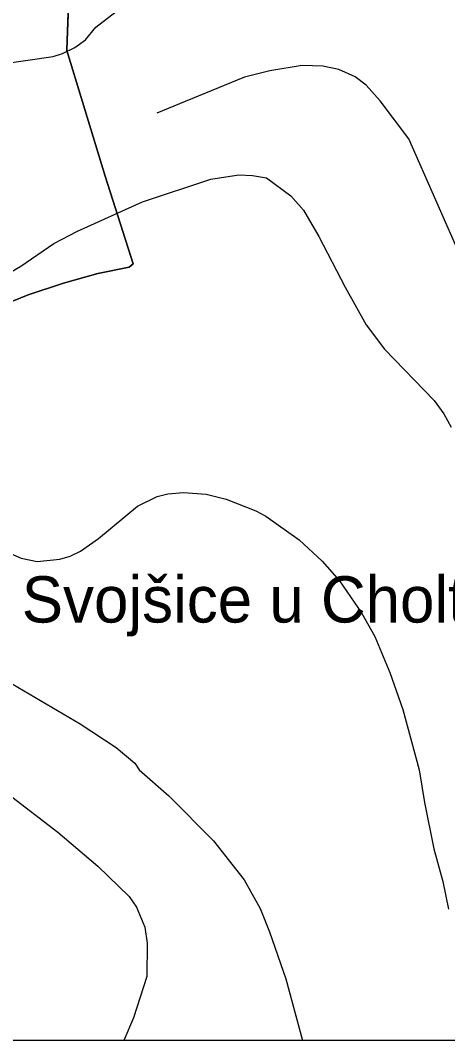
# Model space of a CAD drawing. Extents: x -662620 to -656370, y -1067090 to -1062990.
# Drawn here: x -660856.6 to -660671.9, y -1067089.7 to -1066648.8 of the extents above; entities that cross this region are included whole.
import ezdxf

# ---------------------------------------------------------------- set-up
doc = ezdxf.new("R2010")
doc.units = 0
for name, color, linetype in [('HRANICE_KATASTRÁLNÍHO_ÚZEMÍ', 7, 'Continuous'), ('NÁZEV_K__Ú_', 7, 'Continuous'), ('OBVOD_PÚ', 7, 'Continuous'), ('ORNÁ_PŮDA_-_STÁVAJÍCÍ', 7, 'Continuous'), ('ram', 7, 'Continuous'), ('VRSTEVNICE_ZDŮRAZNĚNÁ', 7, 'Continuous'), ('VRSTEVNICE_ZÁKLADNÍ', 7, 'Continuous')]:
    doc.layers.add(name, color=color, linetype=linetype)

msp = doc.modelspace()

# ---------------------------------------------------------------- linework, layer by layer
at = {"layer": 'HRANICE_KATASTRÁLNÍHO_ÚZEMÍ'}
msp.add_lwpolyline([(-660835.26, -1066626.26), (-660836.34, -1066657.33), (-660836.48, -1066661.71), (-660819.92, -1066716.09), (-660807.8, -1066754), (-660809.6, -1066755.35), (-660823.13, -1066758.13), (-660837.99, -1066762.32), (-660853.18, -1066767.38), (-660870, -1066774.16), (-660885.13, -1066781.19), (-660896.33, -1066786.99), (-660960.7, -1066828.87), (-661014.75, -1066874.85), (-661055.88, -1066910.9), (-661072.7, -1066925.54), (-661106, -1066954.65), (-661122.94, -1066935.93), (-661158.28, -1066916.17), (-661181.17, -1066907.25)], dxfattribs=at)
at = {"layer": 'OBVOD_PÚ'}
for points in [[(-660836.34, -1066657.33), (-660835.26, -1066626.26)], [(-660836.48, -1066661.71), (-660836.34, -1066657.33)], [(-660819.92, -1066716.09), (-660836.48, -1066661.71)], [(-660807.8, -1066754), (-660819.92, -1066716.09)], [(-660823.13, -1066758.13), (-660809.6, -1066755.35)], [(-660809.6, -1066755.35), (-660807.8, -1066754)], [(-660837.99, -1066762.32), (-660823.13, -1066758.13)], [(-660853.18, -1066767.38), (-660837.99, -1066762.32)], [(-660870, -1066774.16), (-660853.18, -1066767.38)]]:
    msp.add_lwpolyline(points, dxfattribs=at)
at = {"layer": 'ORNÁ_PŮDA_-_STÁVAJÍCÍ'}
for p, q in [((-660835.26, -1066626.26), (-660836.34, -1066657.33)), ((-660836.34, -1066657.33), (-660836.48, -1066661.71)), ((-660836.48, -1066661.71), (-660819.92, -1066716.09)), ((-660819.92, -1066716.09), (-660807.8, -1066754)), ((-660809.6, -1066755.35), (-660823.13, -1066758.13)), ((-660807.8, -1066754), (-660809.6, -1066755.35)), ((-660823.13, -1066758.13), (-660837.99, -1066762.32)), ((-660837.99, -1066762.32), (-660853.18, -1066767.38)), ((-660853.18, -1066767.38), (-660870, -1066774.16))]:
    msp.add_line(p, q, dxfattribs=at)
msp.add_lwpolyline([(-660835.26, -1066626.26), (-660836.34, -1066657.33), (-660836.48, -1066661.71), (-660819.92, -1066716.09), (-660807.8, -1066754), (-660809.6, -1066755.35), (-660823.13, -1066758.13), (-660837.99, -1066762.32), (-660853.18, -1066767.38), (-660870, -1066774.16), (-660885.13, -1066781.19), (-660896.33, -1066786.99), (-660960.7, -1066828.87), (-661014.75, -1066874.85), (-661055.88, -1066910.9), (-661072.7, -1066925.54), (-661106, -1066954.65), (-661122.94, -1066935.93), (-661158.28, -1066916.17), (-661181.17, -1066907.25)], dxfattribs=at)
at = {"layer": 'ram'}
msp.add_lwpolyline([(-662620.02, -1067089.66), (-662620.02, -1062989.66), (-656370.02, -1062989.66), (-656370.02, -1067089.66), (-662620.02, -1067089.66)], dxfattribs=at)
at = {"layer": 'VRSTEVNICE_ZDŮRAZNĚNÁ'}
for points in [[(-660856.4, -1066754.98), (-660842.21, -1066745.24), (-660831.89, -1066739.79), (-660803.8, -1066727.18), (-660774.28, -1066717.43), (-660762.24, -1066715.57), (-660756.22, -1066715.86), (-660750.2, -1066716.86), (-660739.74, -1066724.6), (-660734.29, -1066730.76), (-660727.55, -1066742.23), (-660716.23, -1066764.01), (-660707.06, -1066780.35), (-660699.18, -1066790.81), (-660677.68, -1066813.03), (-660673.52, -1066818.76), (-660670.37, -1066824.49)], [(-660880.9, -1066769.31), (-660856.4, -1066754.98)]]:
    msp.add_lwpolyline(points, dxfattribs=at)
at = {"layer": 'VRSTEVNICE_ZÁKLADNÍ'}
for points in [[(-660864.28, -1066667.56), (-660842.5, -1066664.41), (-660838.48, -1066663.12), (-660833.04, -1066660.54), (-660828.45, -1066657.1), (-660824.01, -1066651.65), (-660815.26, -1066644.91)], [(-660864.28, -1066667.56), (-660842.5, -1066664.41), (-660838.48, -1066663.12), (-660833.04, -1066660.54), (-660828.45, -1066657.1), (-660824.01, -1066651.65), (-660815.26, -1066644.91)], [(-660627.31, -1066851.21), (-660635.69, -1066826.21), (-660638.98, -1066813.46), (-660649.8, -1066788.47), (-660652.32, -1066780.96), (-660663.46, -1066756.03), (-660665.33, -1066752.99), (-660688.72, -1066699.95), (-660701.04, -1066683.47), (-660707.06, -1066676.73), (-660711.93, -1066673.15), (-660718.96, -1066670), (-660725.83, -1066668.56), (-660734.86, -1066668.28), (-660748.82, -1066670.51), (-660759.73, -1066673.29), (-660785.45, -1066683.75), (-660797.64, -1066688.91)], [(-660880.33, -1066870.78), (-660856.25, -1066881.24), (-660849.37, -1066882.68), (-660839.63, -1066881.67), (-660835.04, -1066880.24), (-660830.6, -1066878.09), (-660822.86, -1066872.65), (-660805.95, -1066858.74), (-660797.49, -1066854.59), (-660792.91, -1066853.3), (-660786.03, -1066852.72), (-660776.28, -1066853.58), (-660767.68, -1066855.73), (-660754.79, -1066860.75), (-660750.49, -1066863.04), (-660736.15, -1066873.22), (-660726.12, -1066882.53), (-660718.67, -1066890.99), (-660709.21, -1066904.75), (-660703.33, -1066915.07), (-660696.89, -1066930.55), (-660691.3, -1066946.6), (-660684.27, -1066972.68), (-660681.98, -1066986.73), (-660677.82, -1067006.79), (-660673.95, -1067020.83), (-660671.52, -1067032.87)], [(-660880.33, -1066870.78), (-660856.25, -1066881.24), (-660849.37, -1066882.68), (-660839.63, -1066881.67), (-660835.04, -1066880.24), (-660830.6, -1066878.09), (-660822.86, -1066872.65), (-660805.95, -1066858.74), (-660797.49, -1066854.59), (-660792.91, -1066853.3), (-660786.03, -1066852.72), (-660776.28, -1066853.58), (-660767.68, -1066855.73), (-660754.79, -1066860.75), (-660750.49, -1066863.04), (-660736.15, -1066873.22), (-660726.12, -1066882.53), (-660718.67, -1066890.99), (-660709.21, -1066904.75), (-660703.33, -1066915.07), (-660696.89, -1066930.55), (-660691.3, -1066946.6), (-660684.27, -1066972.68), (-660681.98, -1066986.73), (-660677.82, -1067006.79), (-660673.95, -1067020.83), (-660671.52, -1067032.87)], [(-660865.14, -1066932.55), (-660830.74, -1066952.76), (-660815.26, -1066962.93), (-660807.1, -1066969.81), (-660805.23, -1066972.68), (-660792.48, -1066983.86), (-660773.13, -1067003.35), (-660759.94, -1067020.12), (-660752.92, -1067032.59), (-660748.91, -1067042.62), (-660741.89, -1067062.97), (-660734.71, -1067089.66)], [(-660865.14, -1066932.55), (-660830.74, -1066952.76), (-660815.26, -1066962.93), (-660807.1, -1066969.81), (-660805.23, -1066972.68), (-660792.48, -1066983.86), (-660773.13, -1067003.35), (-660759.94, -1067020.12), (-660752.92, -1067032.59), (-660748.91, -1067042.62), (-660741.89, -1067062.97), (-660734.71, -1067089.66)], [(-660884.06, -1066966.09), (-660840.49, -1066999.62), (-660823.15, -1067014.24), (-660809.53, -1067027.43), (-660806.38, -1067032.01), (-660802.8, -1067040.61), (-660801.79, -1067047.49), (-660801.94, -1067061.97), (-660807.67, -1067079.88), (-660811.92, -1067089.66)], [(-660884.06, -1066966.09), (-660840.49, -1066999.62), (-660823.15, -1067014.24), (-660809.53, -1067027.43), (-660806.38, -1067032.01), (-660802.8, -1067040.61), (-660801.79, -1067047.49), (-660801.94, -1067061.97), (-660807.67, -1067079.88), (-660811.92, -1067089.66)]]:
    msp.add_lwpolyline(points, dxfattribs=at)

# ---------------------------------------------------------------- texts
at = {"layer": 'NÁZEV_K__Ú_'}
msp.add_text('k.ú. Svojšice u Choltic', height=20, dxfattribs=at).set_placement((-660906.54, -1066908.99))

doc.saveas('drawing.dxf')
